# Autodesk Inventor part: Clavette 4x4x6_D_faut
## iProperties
Created: 2011-10
Part Number: Clavette 4x4x6_D_faut
Document SubType Name: Modeling
Designer: Bruno
Author: Bruno
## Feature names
1. Base1
